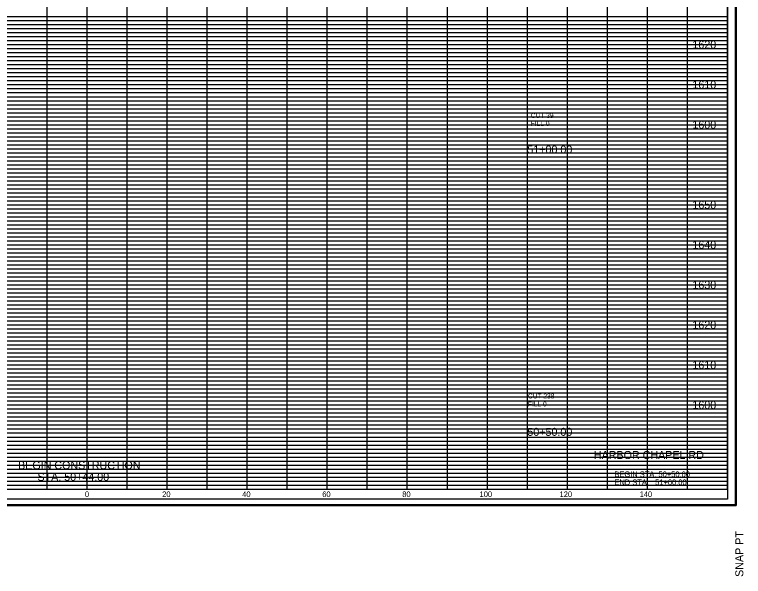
# Model space of a CAD drawing. Extents: x 980 to 1324, y 978 to 1767.
# Drawn here: x 1141.8 to 1324, y 978.2 to 1118.5 of the extents above; entities that cross this region are included whole.
import ezdxf

# ---------------------------------------------------------------- set-up
doc = ezdxf.new("R2010")
doc.units = 0
for name, color, linetype in [('DESIGN - SHEET - Corner Text', 7, 'Continuous'), ('DESIGN - SHEET - Light Grid', 7, 'Continuous'), ('DESIGN - SHEET - Linework', 7, 'Continuous'), ('DESIGN - SHEET - Plot Shape', 7, 'Continuous'), ('DESIGN - TYPICAL - Finished Grade and Subgrade', 7, 'Continuous'), ('DESIGN - TYPICAL - Text', 7, 'Continuous')]:
    doc.layers.add(name, color=color, linetype=linetype)

# ---------------------------------------------------------------- blocks, each defined once
blk = doc.blocks.new('XSTSHT')
at = {"layer": 'DESIGN - SHEET - Light Grid'}
for p, q in [((8, 11.8), (16, 11.8)), ((8, 11.7), (16, 11.7)), ((16, 11.8), (24, 11.8)), ((16, 11.7), (24, 11.7)), ((24, 11.8), (32, 11.8)), ((24, 11.7), (32, 11.7)), ((8, 11.6), (16, 11.6)), ((8, 11.5), (16, 11.5)), ((16, 11.6), (24, 11.6)), ((16, 11.5), (24, 11.5)), ((24, 11.6), (32, 11.6)), ((24, 11.5), (32, 11.5)), ((8, 11.4), (16, 11.4)), ((8, 11.3), (16, 11.3)), ((16, 11.4), (24, 11.4)), ((16, 11.3), (24, 11.3)), ((24, 11.4), (32, 11.4)), ((24, 11.3), (32, 11.3)), ((8, 11.2), (16, 11.2)), ((16, 11.2), (24, 11.2)), ((24, 11.2), (32, 11.2)), ((8, 11.1), (16, 11.1)), ((16, 11.1), (24, 11.1)), ((24, 11.1), (32, 11.1)), ((8, 10.9), (16, 10.9)), ((8, 10.8), (16, 10.8)), ((16, 10.9), (24, 10.9)), ((16, 10.8), (24, 10.8)), ((24, 10.9), (32, 10.9)), ((24, 10.8), (32, 10.8)), ((8, 10.7), (16, 10.7)), ((8, 10.6), (16, 10.6)), ((16, 10.7), (24, 10.7)), ((16, 10.6), (24, 10.6)), ((24, 10.7), (32, 10.7)), ((24, 10.6), (32, 10.6)), ((8, 10.5), (16, 10.5)), ((8, 10.4), (16, 10.4)), ((16, 10.5), (24, 10.5)), ((16, 10.4), (24, 10.4)), ((24, 10.5), (32, 10.5)), ((24, 10.4), (32, 10.4)), ((8, 10.3), (16, 10.3)), ((16, 10.3), (24, 10.3)), ((24, 10.3), (32, 10.3)), ((8, 10.2), (16, 10.2)), ((8, 10.1), (16, 10.1)), ((16, 10.2), (24, 10.2)), ((16, 10.1), (24, 10.1)), ((24, 10.2), (32, 10.2)), ((24, 10.1), (32, 10.1)), ((8, 9.9), (16, 9.9)), ((16, 9.9), (24, 9.9)), ((24, 9.9), (32, 9.9)), ((8, 9.8), (16, 9.8)), ((8, 9.7), (16, 9.7)), ((16, 9.8), (24, 9.8)), ((16, 9.7), (24, 9.7)), ((24, 9.8), (32, 9.8)), ((24, 9.7), (32, 9.7)), ((8, 9.6), (16, 9.6)), ((8, 9.5), (16, 9.5)), ((16, 9.6), (24, 9.6)), ((16, 9.5), (24, 9.5)), ((24, 9.6), (32, 9.6)), ((24, 9.5), (32, 9.5)), ((8, 9.4), (16, 9.4)), ((8, 9.3), (16, 9.3)), ((16, 9.4), (24, 9.4)), ((16, 9.3), (24, 9.3)), ((24, 9.4), (32, 9.4)), ((24, 9.3), (32, 9.3)), ((8, 9.2), (16, 9.2)), ((16, 9.2), (24, 9.2)), ((24, 9.2), (32, 9.2)), ((8, 9.1), (16, 9.1)), ((16, 9.1), (24, 9.1)), ((24, 9.1), (32, 9.1)), ((8, 8.9), (16, 8.9)), ((8, 8.8), (16, 8.8)), ((16, 8.9), (24, 8.9)), ((16, 8.8), (24, 8.8)), ((24, 8.9), (32, 8.9)), ((24, 8.8), (32, 8.8)), ((8, 8.7), (16, 8.7)), ((8, 8.6), (16, 8.6)), ((16, 8.7), (24, 8.7)), ((16, 8.6), (24, 8.6)), ((24, 8.7), (32, 8.7)), ((24, 8.6), (32, 8.6)), ((8, 8.5), (16, 8.5)), ((8, 8.4), (16, 8.4)), ((16, 8.5), (24, 8.5)), ((16, 8.4), (24, 8.4)), ((24, 8.5), (32, 8.5)), ((24, 8.4), (32, 8.4)), ((8, 8.3), (16, 8.3)), ((8, 8.2), (16, 8.2)), ((16, 8.3), (24, 8.3)), ((16, 8.2), (24, 8.2)), ((24, 8.3), (32, 8.3)), ((24, 8.2), (32, 8.2)), ((8, 8.1), (16, 8.1)), ((16, 8.1), (24, 8.1)), ((24, 8.1), (32, 8.1)), ((8, 7.9), (16, 7.9)), ((16, 7.9), (24, 7.9)), ((24, 7.9), (32, 7.9)), ((8, 7.8), (16, 7.8)), ((8, 7.7), (16, 7.7)), ((16, 7.8), (24, 7.8)), ((16, 7.7), (24, 7.7)), ((24, 7.8), (32, 7.8)), ((24, 7.7), (32, 7.7)), ((8, 7.6), (16, 7.6)), ((8, 7.5), (16, 7.5)), ((16, 7.6), (24, 7.6)), ((16, 7.5), (24, 7.5)), ((24, 7.6), (32, 7.6)), ((24, 7.5), (32, 7.5)), ((8, 7.4), (16, 7.4)), ((8, 7.3), (16, 7.3)), ((16, 7.4), (24, 7.4)), ((16, 7.3), (24, 7.3)), ((24, 7.4), (32, 7.4)), ((24, 7.3), (32, 7.3)), ((8, 7.2), (16, 7.2)), ((16, 7.2), (24, 7.2)), ((24, 7.2), (32, 7.2)), ((8, 7.1), (16, 7.1)), ((16, 7.1), (24, 7.1)), ((24, 7.1), (32, 7.1)), ((8, 6.9), (16, 6.9)), ((8, 6.8), (16, 6.8)), ((16, 6.9), (24, 6.9)), ((16, 6.8), (24, 6.8)), ((24, 6.9), (32, 6.9)), ((24, 6.8), (32, 6.8)), ((8, 6.7), (16, 6.7)), ((8, 6.6), (16, 6.6)), ((16, 6.7), (24, 6.7)), ((16, 6.6), (24, 6.6)), ((24, 6.7), (32, 6.7)), ((24, 6.6), (32, 6.6)), ((8, 6.5), (16, 6.5)), ((8, 6.4), (16, 6.4)), ((16, 6.5), (24, 6.5)), ((16, 6.4), (24, 6.4)), ((24, 6.5), (32, 6.5)), ((24, 6.4), (32, 6.4)), ((8, 6.3), (16, 6.3)), ((8, 6.2), (16, 6.2)), ((16, 6.3), (24, 6.3)), ((16, 6.2), (24, 6.2)), ((24, 6.3), (32, 6.3)), ((24, 6.2), (32, 6.2)), ((8, 6.1), (16, 6.1)), ((16, 6.1), (24, 6.1)), ((24, 6.1), (32, 6.1)), ((8, 5.9), (16, 5.9)), ((16, 5.9), (24, 5.9)), ((24, 5.9), (32, 5.9)), ((8, 5.8), (16, 5.8)), ((8, 5.7), (16, 5.7)), ((16, 5.8), (24, 5.8)), ((16, 5.7), (24, 5.7)), ((24, 5.8), (32, 5.8)), ((24, 5.7), (32, 5.7)), ((8, 5.6), (16, 5.6)), ((8, 5.5), (16, 5.5)), ((16, 5.6), (24, 5.6)), ((16, 5.5), (24, 5.5)), ((24, 5.6), (32, 5.6)), ((24, 5.5), (32, 5.5)), ((8, 5.4), (16, 5.4)), ((8, 5.3), (16, 5.3)), ((16, 5.4), (24, 5.4)), ((16, 5.3), (24, 5.3)), ((24, 5.4), (32, 5.4)), ((24, 5.3), (32, 5.3)), ((8, 5.2), (16, 5.2)), ((16, 5.2), (24, 5.2)), ((24, 5.2), (32, 5.2)), ((8, 5.1), (16, 5.1)), ((16, 5.1), (24, 5.1)), ((24, 5.1), (32, 5.1)), ((8, 4.9), (16, 4.9)), ((8, 4.8), (16, 4.8)), ((16, 4.9), (24, 4.9)), ((16, 4.8), (24, 4.8)), ((24, 4.9), (32, 4.9)), ((24, 4.8), (32, 4.8)), ((8, 4.7), (16, 4.7)), ((8, 4.6), (16, 4.6)), ((16, 4.7), (24, 4.7)), ((16, 4.6), (24, 4.6)), ((24, 4.7), (32, 4.7)), ((24, 4.6), (32, 4.6)), ((8, 4.5), (16, 4.5)), ((8, 4.4), (16, 4.4)), ((16, 4.5), (24, 4.5)), ((16, 4.4), (24, 4.4)), ((24, 4.5), (32, 4.5)), ((24, 4.4), (32, 4.4)), ((8, 4.3), (16, 4.3)), ((8, 4.2), (16, 4.2)), ((16, 4.3), (24, 4.3)), ((16, 4.2), (24, 4.2)), ((24, 4.3), (32, 4.3)), ((24, 4.2), (32, 4.2)), ((8, 4.1), (16, 4.1)), ((16, 4.1), (24, 4.1)), ((24, 4.1), (32, 4.1)), ((8, 3.9), (16, 3.9)), ((16, 3.9), (24, 3.9)), ((24, 3.9), (32, 3.9)), ((8, 3.8), (16, 3.8)), ((8, 3.7), (16, 3.7)), ((16, 3.8), (24, 3.8)), ((16, 3.7), (24, 3.7)), ((24, 3.8), (32, 3.8)), ((24, 3.7), (32, 3.7)), ((8, 3.6), (16, 3.6)), ((8, 3.5), (16, 3.5)), ((16, 3.6), (24, 3.6)), ((16, 3.5), (24, 3.5)), ((24, 3.6), (32, 3.6)), ((24, 3.5), (32, 3.5)), ((8, 3.4), (16, 3.4)), ((8, 3.3), (16, 3.3)), ((16, 3.4), (24, 3.4)), ((16, 3.3), (24, 3.3)), ((24, 3.4), (32, 3.4)), ((24, 3.3), (32, 3.3)), ((8, 3.2), (16, 3.2)), ((8, 3.1), (16, 3.1)), ((16, 3.2), (24, 3.2)), ((16, 3.1), (24, 3.1)), ((24, 3.2), (32, 3.2)), ((24, 3.1), (32, 3.1)), ((8, 2.9), (16, 2.9)), ((8, 2.8), (16, 2.8)), ((16, 2.9), (24, 2.9)), ((16, 2.8), (24, 2.8)), ((24, 2.9), (32, 2.9)), ((24, 2.8), (32, 2.8)), ((8, 2.7), (16, 2.7)), ((8, 2.6), (16, 2.6)), ((16, 2.7), (24, 2.7)), ((16, 2.6), (24, 2.6)), ((24, 2.7), (32, 2.7)), ((24, 2.6), (32, 2.6)), ((8, 2.5), (16, 2.5)), ((8, 2.4), (16, 2.4)), ((16, 2.5), (24, 2.5)), ((16, 2.4), (24, 2.4)), ((24, 2.5), (32, 2.5)), ((24, 2.4), (32, 2.4)), ((8, 2.3), (16, 2.3)), ((8, 2.2), (16, 2.2)), ((16, 2.3), (24, 2.3)), ((16, 2.2), (24, 2.2)), ((24, 2.3), (32, 2.3)), ((24, 2.2), (32, 2.2)), ((8, 2.1), (16, 2.1)), ((16, 2.1), (24, 2.1)), ((24, 2.1), (32, 2.1)), ((8, 1.9), (16, 1.9)), ((16, 1.9), (24, 1.9)), ((24, 1.9), (32, 1.9)), ((8, 1.8), (16, 1.8)), ((8, 1.7), (16, 1.7)), ((16, 1.8), (24, 1.8)), ((16, 1.7), (24, 1.7)), ((24, 1.8), (32, 1.8)), ((24, 1.7), (32, 1.7)), ((8, 1.6), (16, 1.6)), ((8, 1.5), (16, 1.5)), ((16, 1.6), (24, 1.6)), ((16, 1.5), (24, 1.5)), ((24, 1.6), (32, 1.6)), ((24, 1.5), (32, 1.5)), ((8, 1.4), (16, 1.4)), ((8, 1.3), (16, 1.3)), ((16, 1.4), (24, 1.4)), ((16, 1.3), (24, 1.3)), ((24, 1.4), (32, 1.4)), ((24, 1.3), (32, 1.3)), ((8, 1.2), (16, 1.2)), ((8, 1.1), (16, 1.1)), ((16, 1.2), (24, 1.2)), ((16, 1.1), (24, 1.1)), ((24, 1.2), (32, 1.2)), ((24, 1.1), (32, 1.1)), ((8, 0.9), (16, 0.9)), ((8, 0.8), (16, 0.8)), ((16, 0.9), (24, 0.9)), ((16, 0.8), (24, 0.8)), ((24, 0.9), (32, 0.9)), ((24, 0.8), (32, 0.8)), ((8, 0.7), (16, 0.7)), ((8, 0.6), (16, 0.6)), ((16, 0.7), (24, 0.7)), ((16, 0.6), (24, 0.6)), ((24, 0.7), (32, 0.7)), ((24, 0.6), (32, 0.6)), ((8, 0.5), (16, 0.5)), ((8, 0.4), (16, 0.4)), ((16, 0.5), (24, 0.5)), ((16, 0.4), (24, 0.4)), ((24, 0.5), (32, 0.5)), ((24, 0.4), (32, 0.4)), ((8, 0.3), (16, 0.3)), ((8, 0.2), (16, 0.2)), ((16, 0.3), (24, 0.3)), ((16, 0.2), (24, 0.2)), ((24, 0.3), (32, 0.3)), ((24, 0.2), (32, 0.2)), ((8, 0.1), (16, 0.1)), ((16, 0.1), (24, 0.1)), ((24, 0.1), (32, 0.1))]:
    blk.add_line(p, q, dxfattribs=at)
at = {"layer": 'DESIGN - SHEET - Linework'}
for p, q in [((32.217, 21.414), (32.217, -0.414)), ((15, 0), (15, 21)), ((16, 0), (16, 21)), ((17, 0), (17, 21)), ((18, 0), (18, 21)), ((19, 0), (19, 21)), ((20, 0), (20, 21)), ((21, 0), (21, 21)), ((22, 0), (22, 21)), ((23, 0), (23, 21)), ((24, 0), (24, 21)), ((25, 0), (25, 21)), ((26, 0), (26, 21)), ((27, 0), (27, 21)), ((28, 0), (28, 20)), ((29, 0), (29, 20)), ((30, 0), (30, 20)), ((31, 0), (31, 20)), ((0, 11), (32, 11)), ((0, 10), (32, 10)), ((0, 9), (32, 9)), ((0, 8), (32, 8)), ((0, 7), (32, 7)), ((0, 6), (32, 6)), ((0, 5), (32, 5)), ((0, 4), (32, 4)), ((0, 3), (32, 3)), ((0, 2), (32, 2)), ((0, 1), (32, 1)), ((-1.823, -0.414), (32.217, -0.414))]:
    blk.add_line(p, q, dxfattribs=at)
blk.add_lwpolyline([(0, 21), (0, 0), (32, 0), (32, 21), (0, 21)], dxfattribs=at)
at = {"layer": 'DESIGN - SHEET - Plot Shape'}
for points in [[(-1.803, 21.394), (32.197, 21.394), (32.197, -0.394), (-1.803, -0.394)], [(-0.85, 21), (32, 21), (32, -0.25), (-0.85, -0.25)]]:
    blk.add_lwpolyline(points, close=True, dxfattribs=at)
at = {"layer": 'DESIGN - SHEET - Corner Text'}
blk.add_text('SNAP PT  ', height=0.2, rotation=90, dxfattribs=at).set_placement((32.397, -2.194))

msp = doc.modelspace()

# ---------------------------------------------------------------- linework, layer by layer
at = {"layer": 'DESIGN - SHEET - Plot Shape'}
msp.add_lwpolyline([(991.5, 1210), (1320, 1210), (1320, 997.5), (991.5, 997.5)], close=True, dxfattribs=at)

# ---------------------------------------------------------------- block references
at = {"layer": 'DESIGN - TYPICAL - Finished Grade and Subgrade', "xscale": 10, "yscale": 10}
msp.add_blockref('XSTSHT', (1000, 1000), dxfattribs=at)

# ---------------------------------------------------------------- texts
at = {"layer": 'DESIGN - SHEET - Corner Text'}
for s, height, p in [('1620', 2, (1311.25, 1110)), ('1610', 2, (1311.25, 1100)), ('1600', 2, (1311.25, 1090)), ('1650', 2, (1311.25, 1070)), ('1640', 2, (1311.25, 1060)), ('1630', 2, (1311.25, 1050)), ('1620', 2, (1311.25, 1040)), ('1610', 2, (1311.25, 1030)), ('1600', 2, (1311.25, 1020)), ('HARBOR CHAPEL RD', 2, (1286.63, 1007.5)), ('BEGIN STA. 50+50.00', 1.4, (1291.75, 1003)), ('END STA.   51+00.00', 1.4, (1291.75, 1001)), ('0', 1.4, (1159.42, 998)), ('0', 1.4, (1159.42, 998)), ('20', 1.4, (1178.74, 998)), ('40', 1.4, (1198.74, 998)), ('60', 1.4, (1218.74, 998)), ('80', 1.4, (1238.74, 998)), ('100', 1.4, (1258.06, 998)), ('120', 1.4, (1278.06, 998)), ('140', 1.4, (1298.06, 998))]:
    msp.add_text(s, height=height, dxfattribs=at).set_placement(p)
at = {"layer": 'DESIGN - TYPICAL - Text'}
for s, height, p in [('CUT 39', 1.2, (1270.84, 1092.68)), ('FILL 0', 1.2, (1270.84, 1090.68)), ('51+00.00', 2, (1270, 1083.81)), ('CUT 238', 1.2, (1270.14, 1022.63)), ('FILL 0', 1.2, (1270.14, 1020.63)), ('50+50.00', 2, (1270, 1013.29)), ('BEGIN CONSTRUCTION', 2, (1142.72, 1004.95)), ('STA. 50+44.00', 2, (1147.57, 1002.05))]:
    msp.add_text(s, height=height, dxfattribs=at).set_placement(p)

doc.saveas('drawing.dxf')
